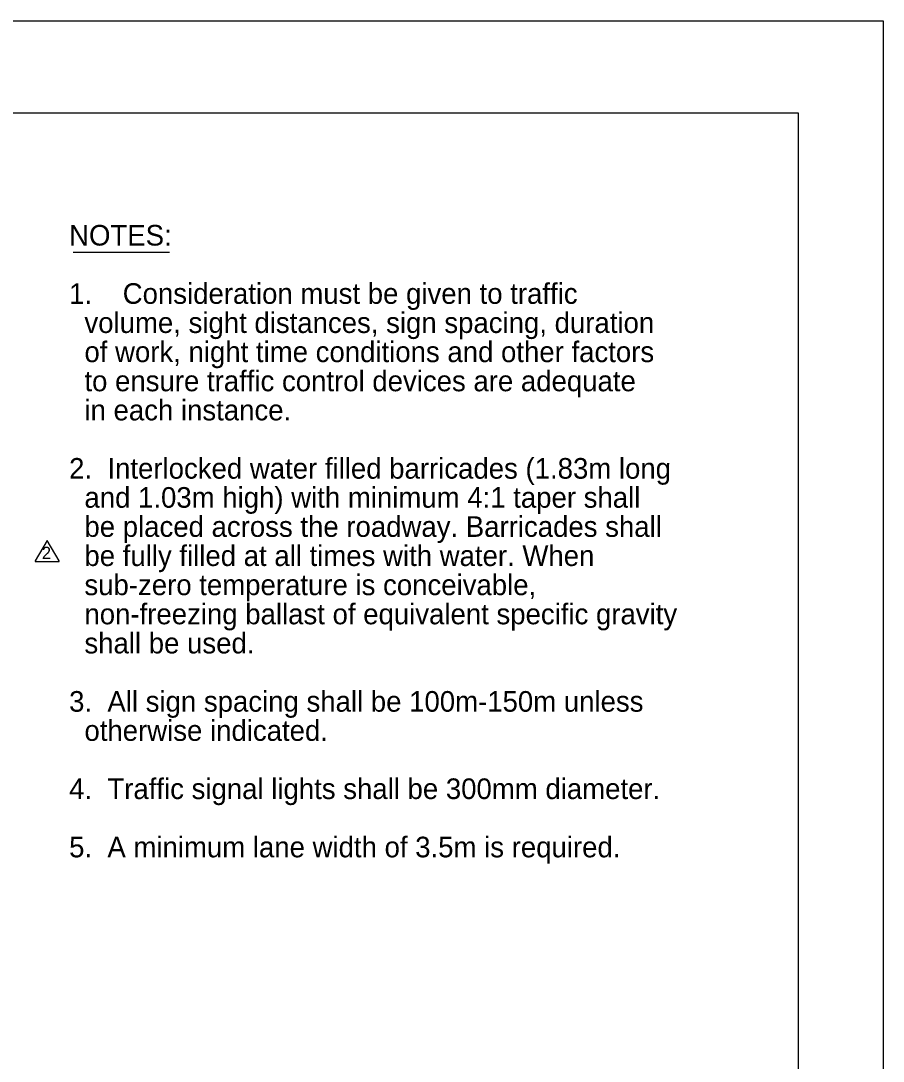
# Model space of a CAD drawing. Extents: x 2170 to 2386, y 134 to 413.
# Drawn here: x 2284.4 to 2385.6, y 290.7 to 412.8 of the extents above; entities that cross this region are included whole.
import ezdxf

# ---------------------------------------------------------------- set-up
doc = ezdxf.new("R2010")
doc.units = 0
for name, color, linetype in [('Level 1', 7, 'Continuous'), ('Level 10', 7, 'Continuous'), ('Level 60', 7, 'Continuous')]:
    doc.layers.add(name, color=color, linetype=linetype)

msp = doc.modelspace()

# ---------------------------------------------------------------- linework, layer by layer
at = {"layer": 'Level 1'}
msp.add_line((2290.53, 385.62), (2301.82, 385.62), dxfattribs=at)
at = {"layer": 'Level 60'}
for points in [[(2169.62, 412.76), (2385.62, 412.76), (2385.62, 133.76), (2169.62, 133.76)], [(2188.75, 401.95), (2375.62, 401.95), (2375.62, 144.57), (2188.75, 144.57)]]:
    msp.add_lwpolyline(points, close=True, dxfattribs=at)
for points in [[(2287.47, 351.78), (2286.08, 349.36)], [(2288.87, 349.36), (2287.47, 351.78)], [(2286.08, 349.36), (2286.05, 349.31), (2288.89, 349.31), (2288.87, 349.36)]]:
    msp.add_lwpolyline(points, dxfattribs=at)

# ---------------------------------------------------------------- texts
at = {"layer": 'Level 10'}
for s, p in [('NOTES:', (2290.05, 386.38)), ('1.    Consideration must be given to traffic', (2290.05, 379.54)), ('  volume, sight distances, sign spacing, duration  ', (2290.05, 376.12)), ('  of work, night time conditions and other factors ', (2290.05, 372.7)), ('  to ensure traffic control devices are adequate  ', (2290.05, 369.28)), ('  in each instance.', (2290.05, 365.86)), ('2.  Interlocked water filled barricades (1.83m long', (2290.05, 359.02)), ('  and 1.03m high) with minimum 4:1 taper shall ', (2290.05, 355.61)), ('  be placed across the roadway. Barricades shall ', (2290.05, 352.19)), ('  be fully filled at all times with water. When ', (2290.05, 348.77)), ('  sub-zero temperature is conceivable, ', (2290.05, 345.35)), ('  non-freezing ballast of equivalent specific gravity', (2290.05, 341.93)), ('  shall be used.    ', (2290.05, 338.51)), ('3.  All sign spacing shall be 100m-150m unless ', (2290.05, 331.67)), ('  otherwise indicated.', (2290.05, 328.25)), ('4.  Traffic signal lights shall be 300mm diameter.', (2290.05, 321.42)), ('5.  A minimum lane width of 3.5m is required.', (2290.05, 314.58))]:
    msp.add_text(s, height=2.419, dxfattribs=at).set_placement(p)
at = {"layer": 'Level 60'}
msp.add_text('2', height=1.45, rotation=360, dxfattribs=at).set_placement((2286.85, 349.58))

doc.saveas('drawing.dxf')
